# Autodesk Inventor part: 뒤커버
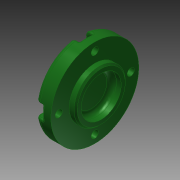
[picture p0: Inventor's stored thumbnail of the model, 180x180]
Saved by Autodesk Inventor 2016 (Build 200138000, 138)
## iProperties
Created: 2015-11
Part Number: 뒤커버
Material: 알루미늄 6061
Document SubType Name: Modeling
Designer: mduedu
Density: 1 g/cm^3
Appearance: 매끄러움 - 짙은 산림 녹색
Author: mduedu
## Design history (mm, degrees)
sketch "스케치1"
  geometry: L1 (-7, 0)-(7, 0); L2 (-7, 0)-(-7, 27.5); L3 (-7, 27.5)-(3, 27.5); L4 (3, 27.5)-(3, 16); L5 (3, 16)-(7, 16); L6 (7, 16)-(7, 0); 2 further points
  constraints: 12 end point, 3 perpendicular, 2 parallel, 1 coincident, 1 horizontal, 1 midpoint
  dimensions: "d0" = 14 distance of L1.start L1.end; "d1" = 55 diameter of L3 L1; "d2" = 4 distance of L4.end L5.end; "d3" = 32 diameter of L5 L1
revolve "회전1" sketch "스케치1" stored, may be unused: angle "d4" = 90 deg
hole "구멍1" diameter "d7" = 25; stored, may be unused: countersink angle "d11" = 90 deg, drill point angle "d13" = 0 deg; dims "d8" = 6, "d9" = 4, "d10" = 2, "d12" = 6, "d61" = 10, "d62" = 10
fillet "모깎기2" dims "d36" = 3
fillet "모깎기3" dims "d37" = 3
sketch "스케치2" dims "d39" = 45
  geometry: C1 r 12.846 at (0, 0) reference; C2 r 24.5 at (0, 0) reference; 6 further points
  constraints: 2 vertical alignment, 1 coincident, 7 other
  dimensions: "d42" = 360 deg dimension on point (0, 0) point (0, 22.5) (derived)
sketch "스케치3"
  geometry: 8 further points
  constraints: 4 coincident
hole "구멍4" sketch "스케치3" at (-22.5, 0), (0, -22.5), (22.5, 0), (0, 22.5) diameter "d44" = 4.5; stored, may be unused: countersink angle "d48" = 90 deg, drill point angle "d50" = 0 deg; dims "d45" = 6, "d46" = 8, "d47" = 4.6, "d49" = 8
sketch "스케치4"
  geometry: L1 (-4, 0)-(-4, -4.708); L2 (4, 0)-(4, -4.708); A1 r 4 centre (0, 0) between (-4, 0) and (4, 0) reference; A2 r 27.5 centre (0, 22.5) between (-4, -4.708) and (4, -4.708) reference; 3 further points
  constraints: 4 end point, 4 point on circle, 2 tangent, 1 parallel, 1 vertical
extrude "돌출1" cut sketch "스케치4" stored distance "d51" = 0; taper "d52" = 0 deg
fillet "모깎기5" dims "d56" = 0.3
fillet "모깎기6" dims "d57" = 1
chamfer "모따기2" distance "d63" = 1; stored, may be unused: second distance "d64" = 2, angle "d65" = 45 deg
node "솔리드1"
pattern_circular "원형 패턴1" dims angle "d54" = 360 deg
